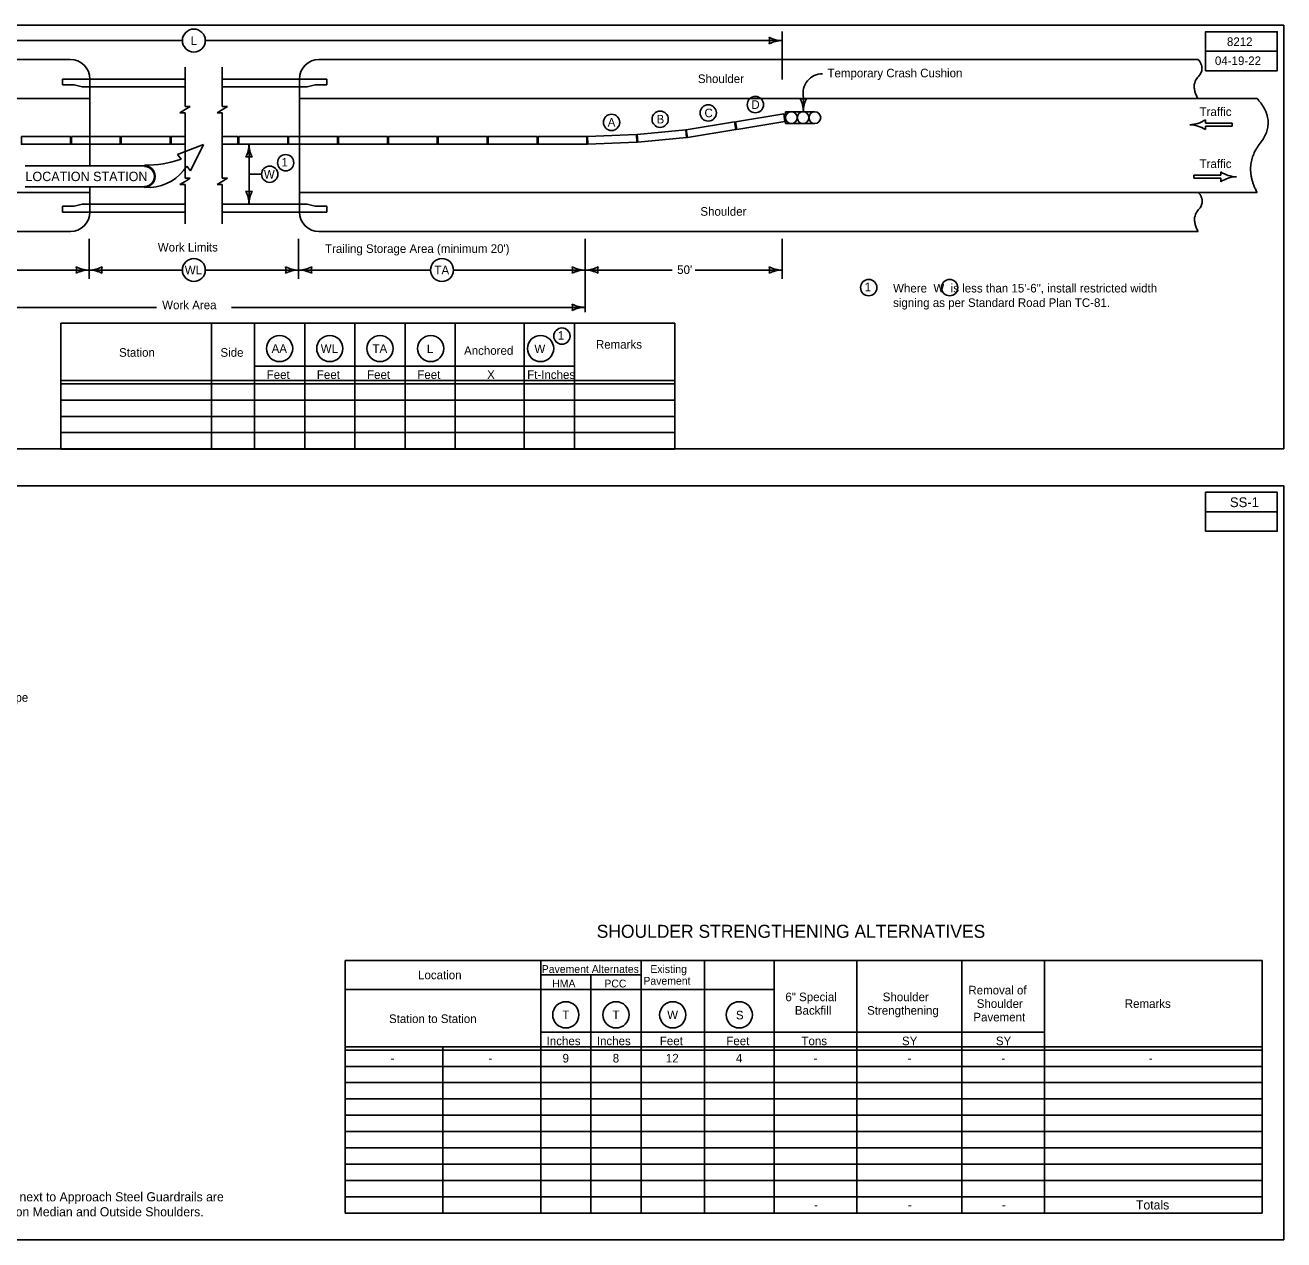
# Model space of a CAD drawing. Extents: x 10148 to 16528, y 8070 to 10905.
# Drawn here: x 14597 to 16528, y 8070 to 9933 of the extents above; entities that cross this region are included whole.
import ezdxf

# ---------------------------------------------------------------- set-up
doc = ezdxf.new("R2010")
doc.units = 0
doc.layers.add('SheetText', color=7, linetype='Continuous')

msp = doc.modelspace()

# ---------------------------------------------------------------- linework, layer by layer
at = {"layer": 'SheetText'}
for p, q in [((13422.6, 9933.4), (16527.5, 9933.4)), ((15758.2, 9923.6), (15758.2, 9850)), ((16527.5, 9933.4), (16527.5, 9283.4)), ((13905.5, 9909.8), (14838.3, 9909.8)), ((14873.3, 9909.8), (15758.2, 9909.8)), ((14886, 9909.8), (15016.5, 9909.8)), ((13537.8, 9880.8), (14666.4, 9880.8)), ((14842.3, 9868.8), (14842.3, 9808.9)), ((14899.4, 9868.8), (14899.4, 9808.9)), ((15047.7, 9880.8), (16396.2, 9880.8)), ((14696.4, 9850.8), (14654.4, 9850.8)), ((14654.4, 9850.8), (14654.4, 9841.8)), ((14696.4, 9850.8), (14842.3, 9850.8)), ((14696.4, 9850.8), (14696.4, 9717.7)), ((14899.4, 9850.8), (15017.7, 9850.8)), ((15017.7, 9850.8), (15059.7, 9850.8)), ((15017.7, 9850.8), (15017.7, 9646.8)), ((15059.7, 9850.8), (15059.7, 9841.8)), ((14654.4, 9841.8), (14672.4, 9841.8)), ((14684.4, 9838.8), (14672.4, 9841.8)), ((14696.4, 9838.8), (14684.4, 9838.8)), ((14696.4, 9838.8), (14842.3, 9838.8)), ((14899.4, 9838.8), (15017.7, 9838.8)), ((15017.7, 9838.8), (15029.7, 9838.8)), ((15029.7, 9838.8), (15041.7, 9841.8)), ((15059.7, 9841.8), (15041.7, 9841.8)), ((13454.3, 9820.8), (14696.4, 9820.8)), ((14842.3, 9803.8), (14850.3, 9808.9)), ((14850.3, 9808.9), (14842.3, 9808.9)), ((14891.4, 9798.8), (14907.4, 9808.9)), ((14907.4, 9808.9), (14899.4, 9808.9)), ((15017.7, 9820.8), (16486.5, 9820.8)), ((15790.6, 9823.4), (15790.6, 9800.9)), ((14834.3, 9798.8), (14842.3, 9803.8)), ((14834.3, 9798.8), (14842.3, 9798.8)), ((14842.3, 9798.8), (14842.3, 9748.8)), ((14891.4, 9798.8), (14899.4, 9798.8)), ((14899.4, 9798.8), (14899.4, 9748.8)), ((15764.4, 9788.3), (15763.1, 9788)), ((15808.2, 9800.6), (15763.2, 9800.6)), ((15763.2, 9800.6), (15763.2, 9782.5)), ((16407.2, 9788.2), (16407.2, 9782.9)), ((15762.6, 9784.6), (15762.6, 9784.6)), ((15763.2, 9782.5), (15808.2, 9782.5)), ((16383.3, 9780.7), (16383.3, 9780.7)), ((16407.2, 9782.9), (16448.5, 9782.9)), ((16448.5, 9778.4), (16407.2, 9778.4)), ((16407.2, 9778.4), (16407.2, 9773.2)), ((16448.5, 9782.9), (16448.5, 9778.4)), ((14830.5, 9735.2), (14870.7, 9750.2)), ((14842.3, 9748.8), (14842.3, 9698.9)), ((14870.7, 9750.2), (14850.6, 9710.2)), ((14899.4, 9748.8), (14899.4, 9698.9)), ((14940.4, 9750.8), (14940.4, 9658.8)), ((14836.4, 9727.9), (14830.5, 9735.2)), ((14780.2, 9717.7), (14597.1, 9717.7)), ((14780.2, 9716.8), (14780.2, 9718.6)), ((14850.6, 9710.2), (14844.9, 9717.2)), ((14834.3, 9688.8), (14842.3, 9693.8)), ((14842.3, 9693.8), (14850.3, 9698.9)), ((14850.3, 9698.9), (14842.3, 9698.9)), ((14891.4, 9688.8), (14907.4, 9698.9)), ((14907.4, 9698.9), (14899.4, 9698.9)), ((14940.4, 9704.8), (14959.7, 9704.8)), ((16430.9, 9703.1), (16389.6, 9703.1)), ((16389.6, 9703.1), (16389.6, 9698.6)), ((16389.6, 9698.6), (16430.9, 9698.6)), ((16430.9, 9708.3), (16430.9, 9703.1)), ((16430.9, 9698.6), (16430.9, 9693.3)), ((16454.8, 9700.8), (16454.8, 9700.8)), ((13454.3, 9676.8), (14696.4, 9676.8)), ((14780.2, 9685.2), (14597.1, 9685.2)), ((14696.4, 9685.2), (14696.4, 9646.8)), ((14780.2, 9684.3), (14780.2, 9686.1)), ((14789.8, 9684.7), (14780.2, 9684.3)), ((14834.3, 9688.8), (14842.3, 9688.8)), ((14842.3, 9688.8), (14842.3, 9628.8)), ((14891.4, 9688.8), (14899.4, 9688.8)), ((14899.4, 9688.8), (14899.4, 9628.8)), ((15017.7, 9676.8), (16486.5, 9676.8)), ((14654.4, 9655.8), (14672.4, 9655.8)), ((14654.4, 9646.8), (14654.4, 9655.8)), ((14684.4, 9658.8), (14672.4, 9655.8)), ((14696.4, 9658.8), (14684.4, 9658.8)), ((14696.4, 9658.8), (14842.3, 9658.8)), ((14899.4, 9658.8), (15017.7, 9658.8)), ((15017.7, 9658.8), (15029.7, 9658.8)), ((15029.7, 9658.8), (15041.7, 9655.8)), ((15059.7, 9655.8), (15041.7, 9655.8)), ((15059.7, 9646.8), (15059.7, 9655.8)), ((14696.4, 9646.8), (14654.4, 9646.8)), ((14696.4, 9646.8), (14842.3, 9646.8)), ((14899.4, 9646.8), (15017.7, 9646.8)), ((15017.7, 9646.8), (15059.7, 9646.8)), ((13537.8, 9616.8), (14666.4, 9616.8)), ((15047.7, 9616.8), (16396.2, 9616.8)), ((14695.1, 9605.5), (14695.1, 9544.3)), ((15016.5, 9605.5), (15016.5, 9544.3)), ((15456, 9605.5), (15456, 9493.2)), ((15758.2, 9605.5), (15758.2, 9544.3)), ((14469, 9557.8), (14695.1, 9557.8)), ((14695.1, 9557.8), (14838.3, 9557.8)), ((14873.3, 9557.8), (15016.5, 9557.8)), ((14886, 9557.8), (15016.5, 9557.8)), ((15016.5, 9557.8), (15218.6, 9557.8)), ((15253.9, 9557.8), (15456, 9557.8)), ((15456, 9557.8), (15589.5, 9557.8)), ((15624.7, 9557.8), (15758.2, 9557.8)), ((14207.6, 9500.6), (14798.4, 9500.6)), ((14913.7, 9500.6), (15456, 9500.6)), ((14915.1, 9500.6), (15016.5, 9500.6)), ((14651.8, 9476.4), (14651.8, 9283.4)), ((14651.8, 9476.4), (15593.4, 9476.4)), ((14651.8, 9283.4), (14651.8, 9476.4)), ((14651.8, 9476.4), (15593.4, 9476.4)), ((14882.8, 9283.4), (14882.8, 9476.4)), ((14948.8, 9283.4), (14948.8, 9476.4)), ((15025.8, 9283.4), (15025.8, 9476.4)), ((15102.8, 9283.4), (15102.8, 9476.4)), ((15179.8, 9283.4), (15179.8, 9476.4)), ((15256.8, 9283.4), (15256.8, 9476.4)), ((15256.8, 9476.4), (15256.8, 9283.4)), ((15362.4, 9283.4), (15362.4, 9476.4)), ((15362.4, 9476.4), (15362.4, 9283.4)), ((15439.4, 9283.4), (15439.4, 9476.4)), ((15439.4, 9476.4), (15439.4, 9283.4)), ((15593.4, 9283.4), (15593.4, 9476.4)), ((15593.4, 9476.4), (15593.4, 9283.4)), ((14948.8, 9410.6), (15439.4, 9410.6)), ((14651.8, 9388.4), (15593.4, 9388.4)), ((14651.8, 9383.4), (15593.4, 9383.4)), ((14651.8, 9358.4), (15593.4, 9358.4)), ((14651.8, 9333.4), (15593.4, 9333.4)), ((14651.8, 9308.4), (15593.4, 9308.4)), ((16527.5, 9283.4), (13422.6, 9283.4)), ((14651.8, 9283.1), (15593.4, 9283.1)), ((15087.8, 8498.9), (15087.8, 8111.5)), ((15087.8, 8498.9), (16494.5, 8498.9)), ((15387.8, 8111.5), (15387.8, 8498.9)), ((15541.8, 8111.5), (15541.8, 8498.9)), ((15638.8, 8111.5), (15638.8, 8498.9)), ((15745.8, 8111.5), (15745.8, 8498.9)), ((15872.4, 8111.5), (15872.4, 8498.9)), ((16033.9, 8111.5), (16033.9, 8498.9)), ((16160.5, 8111.5), (16160.5, 8498.9)), ((16494.5, 8111.5), (16494.5, 8498.9)), ((15387.8, 8476.7), (15541.8, 8476.7)), ((15464.8, 8111.5), (15464.8, 8476.7)), ((15087.8, 8454.5), (15745.8, 8454.5)), ((15387.8, 8388.7), (16160.5, 8388.7)), ((15087.8, 8366.5), (16494.5, 8366.5)), ((15087.8, 8361.5), (16494.5, 8361.5)), ((15237.8, 8111.5), (15237.8, 8366.5)), ((15087.8, 8336.5), (16494.5, 8336.5)), ((15087.8, 8311.5), (16494.5, 8311.5)), ((15087.8, 8286.5), (16494.5, 8286.5)), ((15087.8, 8261.5), (16494.5, 8261.5)), ((15087.8, 8236.5), (16494.5, 8236.5)), ((15087.8, 8211.5), (16494.5, 8211.5)), ((15087.8, 8186.5), (16494.5, 8186.5)), ((15087.8, 8161.5), (16494.5, 8161.5)), ((15087.8, 8136.5), (16494.5, 8136.5)), ((15087.8, 8111.5), (16494.5, 8111.5))]:
    msp.add_line(p, q, dxfattribs=at)
for points in [[(16517.5, 9923.4), (16517.5, 9863.4), (16407.5, 9863.4), (16407.5, 9923.4), (16517.5, 9923.4), (16517.5, 9893.4), (16407.5, 9893.4)], [(14842.3, 9750.8), (14820.9, 9750.8), (14820.9, 9762.8), (14842.3, 9762.8)], [(14842.3, 9762.8), (14842.3, 9750.8)], [(14899.4, 9750.8), (14899.4, 9762.8)], [(14899.4, 9762.8), (14923.2, 9762.8), (14923.2, 9750.8), (14899.4, 9750.8)], [(16517.5, 9217.1), (16517.5, 9157.2), (16407.5, 9157.2), (16407.5, 9217.1), (16517.5, 9217.1), (16517.5, 9187.2), (16407.5, 9187.2)]]:
    msp.add_lwpolyline(points, dxfattribs=at)
for points in [[(15686.4, 9785.3), (15760.5, 9797.5), (15762.4, 9785.6), (15688.4, 9773.5)], [(15535.5, 9765.7), (15610.2, 9772.8), (15611.3, 9760.9), (15536.7, 9753.8)], [(15611, 9773), (15685, 9785.1), (15686.9, 9773.2), (15612.9, 9761.1)], [(14591.4, 9762.8), (14666.4, 9762.8), (14666.4, 9750.8), (14591.4, 9750.8)], [(14667.9, 9762.8), (14742.9, 9762.8), (14742.9, 9750.8), (14667.9, 9750.8)], [(14744.4, 9762.8), (14819.4, 9762.8), (14819.4, 9750.8), (14744.4, 9750.8)], [(14924.7, 9762.8), (14999.7, 9762.8), (14999.7, 9750.8), (14924.7, 9750.8)], [(15001.2, 9762.8), (15076.2, 9762.8), (15076.2, 9750.8), (15001.2, 9750.8)], [(15077.7, 9762.8), (15152.7, 9762.8), (15152.7, 9750.8), (15077.7, 9750.8)], [(15154.2, 9762.8), (15229.2, 9762.8), (15229.2, 9750.8), (15154.2, 9750.8)], [(15230.7, 9762.8), (15305.7, 9762.8), (15305.7, 9750.8), (15230.7, 9750.8)], [(15307.2, 9762.8), (15382.2, 9762.8), (15382.2, 9750.8), (15307.2, 9750.8)], [(15383.7, 9762.8), (15458.7, 9762.8), (15458.7, 9750.8), (15383.7, 9750.8)], [(15459.8, 9762.8), (15534.7, 9765.8), (15535.2, 9753.8), (15460.2, 9750.8)], [(13422.6, 9227.1), (16527.5, 9227.1), (16527.5, 8070.4), (13422.6, 8070.4)]]:
    msp.add_lwpolyline(points, close=True, dxfattribs=at)
for centre, radius in [((14855.8, 9909.8), 17.6), ((15644.7, 9798.8), 12.5), ((15717.1, 9811.5), 12.5), ((15496.4, 9784.3), 12.5), ((15571, 9789.2), 12.5), ((15772.2, 9791.6), 9), ((15772.2, 9791.6), 9), ((15790.2, 9791.6), 9), ((15790.2, 9791.6), 9), ((15808.2, 9791.6), 9), ((15808.2, 9791.6), 9), ((14996.6, 9722.4), 12.5), ((14972.2, 9704.8), 12.5), ((14855.8, 9557.8), 17.6), ((15236.3, 9557.8), 17.6), ((15890.9, 9530.9), 12.5), ((16015, 9530.9), 12.5), ((15420.3, 9456.5), 12.5), ((14987.3, 9437.4), 20.1), ((15064.3, 9437.4), 20.1), ((15141.3, 9437.4), 20.1), ((15219.1, 9437.4), 20.1), ((15387.6, 9437.4), 20.1), ((15426.3, 8415.5), 20.1), ((15503.3, 8415.5), 20.1), ((15590.3, 8415.5), 20.1), ((15692.3, 8415.5), 20.1)]:
    msp.add_circle(centre, radius, dxfattribs=at)
for centre, radius, start, end in [((15722.5, 9909.8), 16.4, 342.2666, 17.7333), ((15758.2, 9952.3), 42.5, 241.9275, 270), ((15758.2, 9867.3), 42.5, 90, 118.0725), ((14666.4, 9850.8), 30, 0, 90), ((15047.7, 9850.8), 30, 90, 180), ((15820.1, 9828.8), 30, 90, 190.3537), ((15790.6, 9836.6), 16.4, 252.2666, 287.7334), ((15748.1, 9800.9), 42.5, 0, 28.0725), ((15833.1, 9800.9), 42.5, 151.9275, 180), ((16381.3, 9829), 48.4, 272.352, 302.382), ((16381.3, 9732.4), 48.4, 57.618, 87.648), ((14897.9, 9750.8), 42.5, 331.9275, 360), ((14982.9, 9750.8), 42.5, 180, 208.0725), ((14940.4, 9715.2), 16.4, 72.2666, 107.7334), ((16456.8, 9749.1), 48.4, 237.618, 267.648), ((16456.8, 9652.5), 48.4, 92.352, 122.382), ((14940.4, 9694.5), 16.4, 252.2666, 287.7333), ((14897.9, 9658.8), 42.5, 360, 28.0725), ((14982.9, 9658.8), 42.5, 151.9275, 180), ((14666.4, 9646.8), 30, 270, 360), ((15047.7, 9646.8), 30, 180, 270), ((14659.5, 9557.8), 16.4, 342.2666, 17.7333), ((14695.1, 9600.3), 42.5, 241.9275, 270), ((14695.1, 9515.3), 42.5, 90, 118.0725), ((14695.1, 9600.3), 42.5, 270, 298.0725), ((14695.1, 9515.3), 42.5, 61.9275, 90), ((14730.8, 9557.8), 16.4, 162.2666, 197.7334), ((14980.9, 9557.8), 16.4, 342.2666, 17.7333), ((15016.5, 9600.3), 42.5, 241.9275, 270), ((15016.5, 9515.3), 42.5, 90, 118.0725), ((15016.5, 9600.3), 42.5, 270, 298.0725), ((15016.5, 9515.3), 42.5, 61.9275, 90), ((15052.2, 9557.8), 16.4, 162.2666, 197.7334), ((15420.4, 9557.8), 16.4, 342.2666, 17.7333), ((15456, 9600.3), 42.5, 241.9275, 270), ((15456, 9515.3), 42.5, 90, 118.0725), ((15456, 9600.3), 42.5, 270, 298.0725), ((15456, 9515.3), 42.5, 61.9275, 90), ((15491.7, 9557.8), 16.4, 162.2666, 197.7334), ((15722.5, 9557.8), 16.4, 342.2666, 17.7333), ((15758.2, 9600.3), 42.5, 241.9275, 270), ((15758.2, 9515.3), 42.5, 90, 118.0725), ((15420.4, 9500.6), 16.4, 342.2666, 17.7333), ((15456, 9543.1), 42.5, 241.9275, 270), ((15456, 9458.1), 42.5, 90, 118.0725)]:
    msp.add_arc(centre, radius, start, end, dxfattribs=at)
for centre, major_axis, start_param, end_param in [((14783.1, 9874.7), (156.9, 0), 4.694293, 5.059134), ((14780.2, 9701.4), (16.3, 0), 4.712389, 7.853982), ((14780.2, 9701.4), (-15.4, 0), 1.570796, 4.712389), ((14785.2, 9754.9), (70.8, 0), 4.776871, 5.71778)]:
    msp.add_ellipse(centre, major_axis=major_axis, ratio=0.995025, start_param=start_param, end_param=end_param, dxfattribs=at)
for points in [[(16396.2, 9880.8), (16408, 9866.7), (16384.3, 9841.7), (16395.7, 9820.8)], [(16486.5, 9820.8), (16518, 9786.4), (16464.6, 9718.3), (16486.5, 9676.8)], [(16396.6, 9676.8), (16408.4, 9662.7), (16384.8, 9637.7), (16396.2, 9616.8)]]:
    msp.add_open_spline(points, degree=2, dxfattribs=at)

# ---------------------------------------------------------------- texts
for s, height, p in [('L', 13.2, (14851, 9903.2)), ('8212', 13.2, (16440.3, 9901.4)), ('04-19-22', 13.2, (16421.9, 9872.2)), ('Temporary Crash Cushion', 13.2, (15827.6, 9853.4)), ('Shoulder', 13.2, (15628.9, 9844.6)), ('D', 13.2, (15710.8, 9804.9)), ('Traffic', 13.2, (16398.3, 9794.1)), ('A', 13.2, (15490.5, 9777.7)), ('B', 13.2, (15565.5, 9782.6)), ('C', 13.2, (15639, 9792.2)), ('1', 13.2, (14990.3, 9716.7)), ('W', 13.2, (14963.2, 9698.2)), ('Traffic', 13.2, (16398.3, 9714.2)), ('LOCATION STATION', 14.4, (14597.5, 9694.2)), ('Shoulder', 13.2, (15632.7, 9641.1)), ('Work Limits', 13.2, (14800.5, 9586.2)), ("Trailing Storage Area (minimum 20')", 13.2, (15057, 9584.1)), ('WL', 13.2, (14841.9, 9551.2)), ('TA', 13.2, (15224.8, 9551.2)), ("50'", 13.2, (15597.1, 9551.8)), ('1', 13.2, (15884.6, 9525.2)), ('Where  W  is less than 15\'-6", install restricted width', 13.2, (15928.3, 9523.4)), ('Work Area', 13.2, (14807.2, 9497.7)), ('signing as per Standard Road Plan TC-81.', 13.2, (15928.3, 9501.2)), ('1', 13.2, (15414, 9450.9)), ('AA', 13.2, (14975.1, 9430.8)), ('WL', 13.2, (15050.4, 9430.8)), ('TA', 13.2, (15129.8, 9430.8)), ('L', 13.2, (15213.2, 9430.4)), ('Anchored', 13.2, (15270.2, 9427.8)), ('W', 13.2, (15378.1, 9430.4)), ('Remarks', 13.2, (15472.5, 9437.2)), ('Station', 13.2, (14741.1, 9424.8)), ('Side', 13.2, (14896.6, 9424.8)), ('Feet', 13.2, (14967.5, 9390.8)), ('Feet', 13.2, (15044.5, 9390.8)), ('Feet', 13.2, (15121.5, 9390.8)), ('Feet', 13.2, (15198.5, 9390.8)), ('X', 13.2, (15305.6, 9390.8)), ('Ft-Inches', 13.2, (15367, 9390.8)), ('SS-1', 15, (16444.8, 9194.2)), ('Foreslope', 13.2, (14523.3, 8895.7)), ('SHOULDER STRENGTHENING ALTERNATIVES', 20, (15473.7, 8533.6)), ('Location', 13.2, (15199.7, 8470.1)), ('Pavement Alternates', 12, (15389.4, 8479.7)), ('Existing ', 12, (15555.9, 8479.7)), ('Width of', 0.01, (15692.3, 8476.7)), ('Strengthening', 0.01, (15692.3, 8476.7)), ('HMA', 12, (15405.4, 8457.5)), ('PCC', 12, (15485.4, 8457.5)), ('Pavement', 12, (15545.3, 8461.7)), ('Removal of ', 13.2, (16043.7, 8446.8)), ('6" Special ', 13.2, (15763.1, 8436.4)), ('Shoulder ', 13.2, (15912.4, 8436.4)), ('Shoulder ', 13.2, (16056.6, 8426.1)), ('Remarks', 13.2, (16283.6, 8426.1)), ('T', 13.2, (15420.9, 8408.9)), ('T', 13.2, (15497.9, 8408.9)), ('W', 13.2, (15581.8, 8408.9)), ('S', 13.2, (15687.2, 8408.5)), ('Backfill', 13.2, (15777.6, 8415.7)), ('Strengthening', 13.2, (15888.4, 8415.7)), ('Pavement', 13.2, (16051.4, 8405.4)), ('Station to Station', 13.2, (15155.1, 8402.9)), ('Inches', 13.2, (15396.9, 8368.9)), ('Inches', 13.2, (15473.9, 8368.9)), ('Feet', 13.2, (15570.5, 8368.9)), ('Feet', 13.2, (15672.5, 8368.9)), ('Tons', 13.2, (15787.7, 8368.9)), ('SY', 13.2, (15941.9, 8368.9)), ('SY', 13.2, (16085.9, 8368.9)), ('-', 13.2, (15157.6, 8342.4)), ('-', 13.2, (15307.6, 8342.4)), ('9', 13.2, (15421.3, 8342.4)), ('8', 13.2, (15498.3, 8342.4)), ('12', 13.2, (15579.8, 8342.4)), ('4', 13.2, (15687.2, 8342.4)), ('-', 13.2, (15806.4, 8342.4)), ('-', 13.2, (15950.5, 8342.4)), ('-', 13.2, (16094.5, 8342.4)), ('-', 13.2, (16320.4, 8342.4)), ('* Existing Paved Shoulders next to Approach Steel Guardrails are ', 14, (14357.4, 8129.4)), ('Totals', 14, (16300.8, 8117)), ('6" Thick, Paved Full-Width on Median and Outside Shoulders.', 14, (14357.4, 8106.4)), ('-', 14, (15806.9, 8117)), ('-', 14, (15950.9, 8117)), ('-', 14, (16095, 8117))]:
    msp.add_text(s, height=height, dxfattribs=at).set_placement(p)

doc.saveas('drawing.dxf')
